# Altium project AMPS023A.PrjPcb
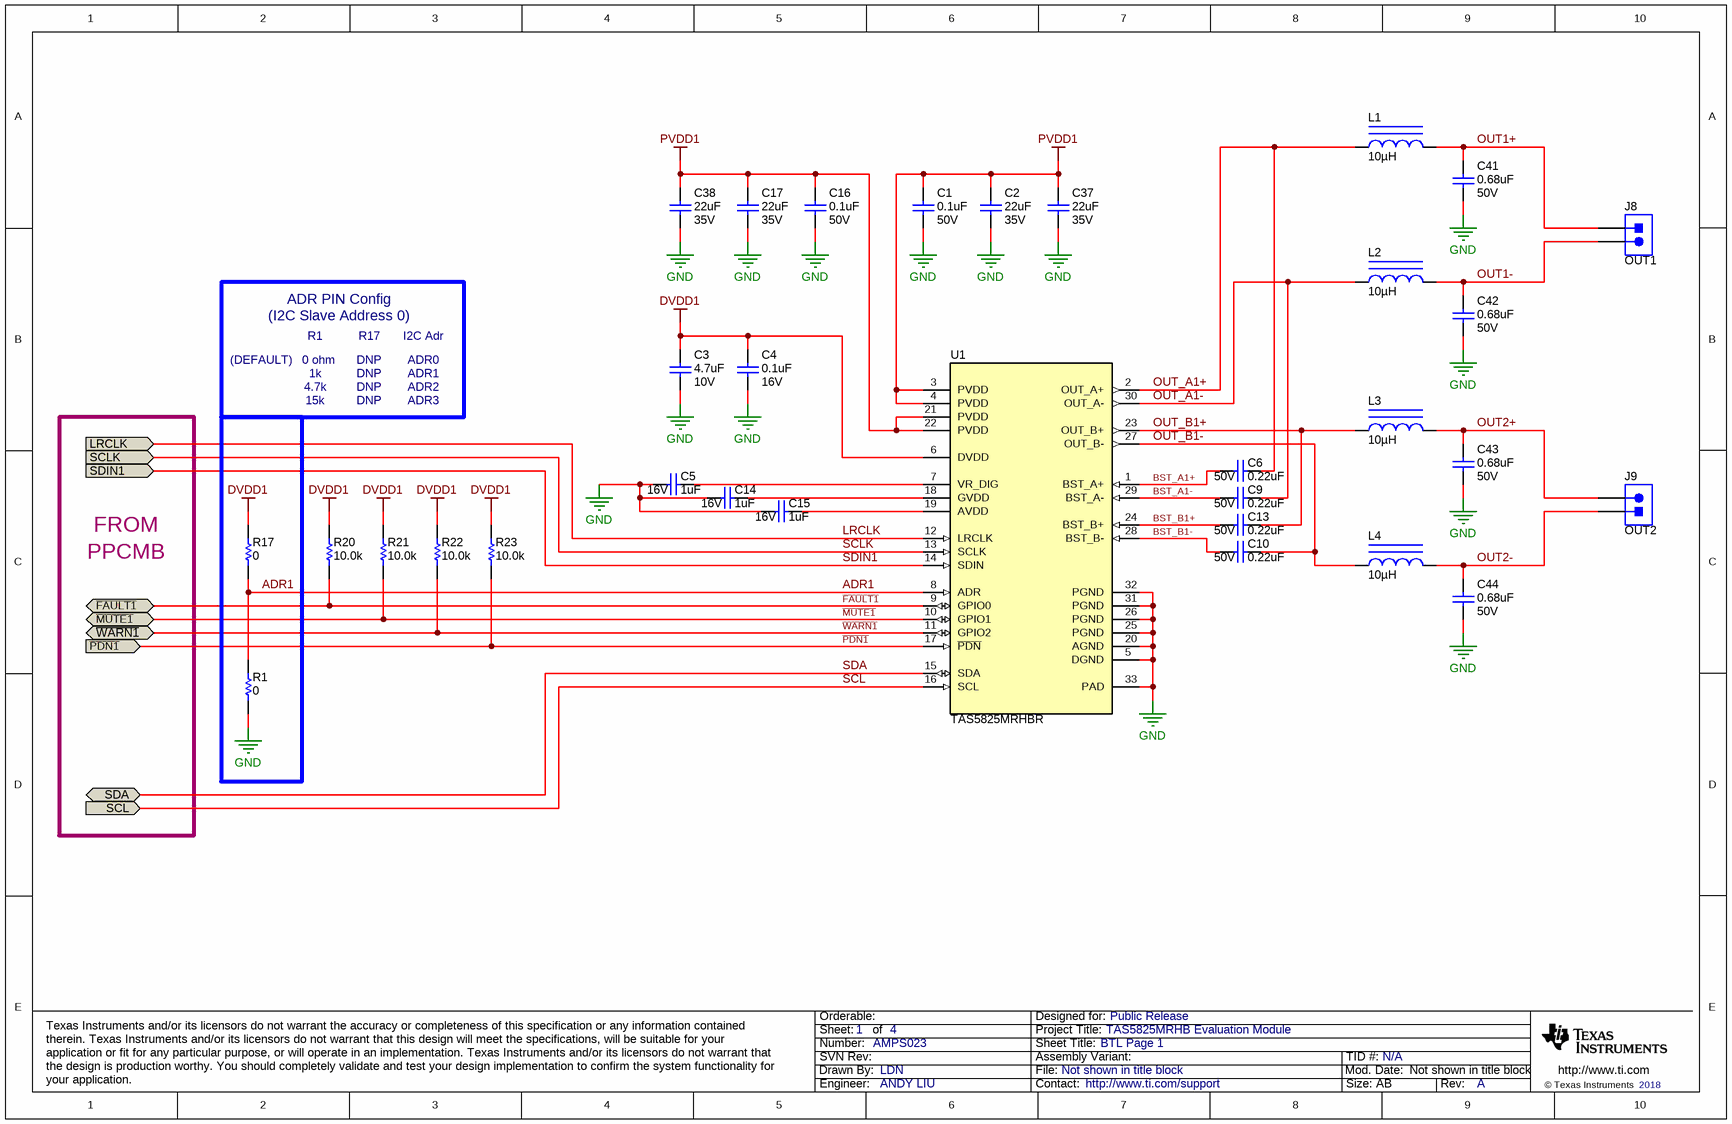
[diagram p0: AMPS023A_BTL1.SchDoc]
CopyrightYear: 2018; PCB_Layout: LDN; PCB_Rev: A; PRJ_Customer: Public Release; PRJ_Engineer: ANDY LIU; PRJ_Number: AMPS023; PRJ_Title: TAS5825MRHB Evaluation Module; SCH_Rev: A; TechSupport: http://www.ti.com/support; TID: N/A
4 sheets, 140 parts. Net scope: flat (ports and power ports of the same name join across sheets).
Board file: AMPS023A_PCB.PcbDoc
Sheets:
  AMPS023A_BTL1.SchDoc
  AMPS023A_BTL2.SchDoc
  AMPS023A_PPCMB-IO.SchDoc
  AMPS023A_EVM_Hardware.SchDoc

## Sheet AMPS023A_BTL1.SchDoc: BTL Page 1
size 323 x 209 mm; Date: Not shown in title block; ApprovedBy: Not shown in title block; CheckedBy: Not shown in title block; Author: Not shown in title block; CompanyName: Not shown in title block; DrawnBy: LDN; Engineer: Not shown in title block; Organization: Not shown in title block; Address1: Not shown in title block; Address2: Not shown in title block; Address3: Not shown in title block; Address4: Not shown in title block; DocumentNumber: 1; Revision: Use project parameter SCH_Rev; SheetNumber: 1; SheetTotal: 4; PageSetup: Record=PageOptions¦CenterHorizontal=True¦CenterVertical=True¦PrintScale=1.00¦XCorrection=1.00¦YCorrection=1.00¦PrintKind=0¦BorderSize=5000000¦LeftOffset=0¦BottomOffset=0¦Orientation=2¦PaperLength=1000¦PaperWidth=1000¦Scale=100¦PaperSource=15¦PrintQuality=600¦MediaType=1¦DitherType=10¦PaperKind=Letter¦PrintScaleMode=1

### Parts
C1  VDC_V: 50V  ValueDisplayed: 0.1uF  [0402L]  (hidden comment: C1005X7R1H104K050BB)
C2  VDC_V: 35V  ValueDisplayed: 22uF  [0805_KTR]  (hidden comment: C2012JB1V226M125AC)
C3  VDC_V: 10V  ValueDisplayed: 4.7uF  [0603L]  (hidden comment: C0603C475K8PACTU)
C4  VDC_V: 16V  ValueDisplayed: 0.1uF  [0603L]  (hidden comment: C0603C104K4RACTU)
C5  VDC_V: 16V  ValueDisplayed: 1uF  [0603L]  (hidden comment: C0603C105K4PACTU)
C6  VDC_V: 50V  ValueDisplayed: 0.22uF  [0603L]  (hidden comment: C1608X7R1H224K080AB)
C9  VDC_V: 50V  ValueDisplayed: 0.22uF  [0603L]  (hidden comment: C1608X7R1H224K080AB)
C10  VDC_V: 50V  ValueDisplayed: 0.22uF  [0603L]  (hidden comment: C1608X7R1H224K080AB)
C13  VDC_V: 50V  ValueDisplayed: 0.22uF  [0603L]  (hidden comment: C1608X7R1H224K080AB)
C14  VDC_V: 16V  ValueDisplayed: 1uF  [0603L]  (hidden comment: C0603C105K4PACTU)
C15  VDC_V: 16V  ValueDisplayed: 1uF  [0603L]  (hidden comment: C0603C105K4PACTU)
C16  VDC_V: 50V  ValueDisplayed: 0.1uF  [0402L]  (hidden comment: C1005X7R1H104K050BB)
C17  VDC_V: 35V  ValueDisplayed: 22uF  [0805_KTR]  (hidden comment: C2012JB1V226M125AC)
C37  VDC_V: 35V  ValueDisplayed: 22uF  [0805_KTR]  (hidden comment: C2012JB1V226M125AC)
C38  VDC_V: 35V  ValueDisplayed: 22uF  [0805_KTR]  (hidden comment: C2012JB1V226M125AC)
C41  VDC_V: 50V  ValueDisplayed: 0.68uF  [0805_KTR]  (hidden comment: C0805C684K5RACTU)
C42  VDC_V: 50V  ValueDisplayed: 0.68uF  [0805_KTR]  (hidden comment: C0805C684K5RACTU)
C43  VDC_V: 50V  ValueDisplayed: 0.68uF  [0805_KTR]  (hidden comment: C0805C684K5RACTU)
C44  VDC_V: 50V  ValueDisplayed: 0.68uF  [0805_KTR]  (hidden comment: C0805C684K5RACTU)
J8  OUT1  [JST_B2PS-VH]
J9  OUT2  [JST_B2PS-VH]
L1  ValueDisplayed: 10µH  [DEM10050C]  (hidden comment: 1274AS-H-100M=P3)
L2  ValueDisplayed: 10µH  [DEM10050C]  (hidden comment: 1274AS-H-100M=P3)
L3  ValueDisplayed: 10µH  [DEM10050C]  (hidden comment: 1274AS-H-100M=P3)
L4  ValueDisplayed: 10µH  [DEM10050C]  (hidden comment: 1274AS-H-100M=P3)
R1  ValueDisplayed: 0  [0402L]
R17  ValueDisplayed: 0  [0402L]  (hidden comment: DNP)
R20  ValueDisplayed: 10.0k  [0402L]  (hidden comment: RMCF0402FT10K0)
R21  ValueDisplayed: 10.0k  [0402L]  (hidden comment: RMCF0402FT10K0)
R22  ValueDisplayed: 10.0k  [0402L]  (hidden comment: RMCF0402FT10K0)
R23  ValueDisplayed: 10.0k  [0402L]  (hidden comment: RMCF0402FT10K0)
U1  TAS5825MRHBR  [RHB0032N]

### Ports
LRCLK (in), SCL (in), SCLK (in), SDA (bidir), SDIN1 (in), ~{FAULT1} (bidir), ~{MUTE1} (bidir), ~{PDN1} (in), ~{WARN1} (bidir)

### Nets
DVDD1: C3.2 C4.1 R17.2 R20.2 R21.2 R22.2 R23.2 U1.6(DVDD)
GND: C1.2 C2.1 C3.1 C4.2 C5.2 C14.2 C15.2 C16.2 C17.1 C37.1 C38.1 C41.2 C42.2 C43.2 C44.2 R1.2 U1.5(DGND) U1.20(AGND) U1.25(PGND) U1.26(PGND) U1.31(PGND) U1.32(PGND) U1.33(PAD)
PVDD1: C1.1 C2.2 C16.1 C17.2 C37.2 C38.2 U1.3(PVDD) U1.4(PVDD) U1.21(PVDD) U1.22(PVDD)
~{FAULT1}: R20.1 U1.9(GPIO0) ; port ~{FAULT1}
~{MUTE1}: R21.1 U1.10(GPIO1) ; port ~{MUTE1}
~{PDN1}: R23.1 U1.17(~{PDN}) ; port ~{PDN1}
~{WARN1}: R22.1 U1.11(GPIO2) ; port ~{WARN1}
ADR1: R1.1 R17.1 U1.8(ADR)
BST_A1+: C6.1 U1.1(BST_A+)
BST_A1-: C9.1 U1.29(BST_A-)
BST_B1+: C13.1 U1.24(BST_B+)
BST_B1-: C10.1 U1.28(BST_B-)
LRCLK: U1.12(LRCLK) ; port LRCLK
OUT1+: C41.1 J8.1 L1.2
OUT1-: C42.1 J8.2 L2.2
OUT2+: C43.1 J9.2 L3.2
OUT2-: C44.1 J9.1 L4.2
OUT_A1+: C6.2 L1.1 U1.2(OUT_A+)
OUT_A1-: C9.2 L2.1 U1.30(OUT_A-)
OUT_B1+: C13.2 L3.1 U1.23(OUT_B+)
OUT_B1-: C10.2 L4.1 U1.27(OUT_B-)
SCL: U1.16(SCL) ; port SCL
SCLK: U1.13(SCLK) ; port SCLK
SDA: U1.15(SDA) ; port SDA
SDIN1: U1.14(SDIN) ; port SDIN1
NetC5_1: C5.1 U1.7(VR_DIG)
NetC14_1: C14.1 U1.18(GVDD)
NetC15_1: C15.1 U1.19(AVDD)

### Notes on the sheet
- R1
- (I2C Slave Address 0)
- ADR PIN Config
- R17
- I2C Adr
- (DEFAULT)
- 1k
- 4.7k
- 15k
- 0 ohm
- DNP
- ADR0
- ADR1
- ADR2
- ADR3
- FROM
- PPCMB

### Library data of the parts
C1 C16 = CMP-0006297-2: CAP, CERM, 0.1 uF, 50 V, +/- 10%, X7R, 0402; Manufacturer: TDK; TaMin_C: -55°C; ESR_ohm: 0.039064; Polarized: N; SizeAreaWB_mm2: 3; Value1: 0.039064 ohm; U/M: EA; Value: 0.1uF; TaMax_C: 125°C; SizeZ_mm: 0.6; SizeX_mm: 1; SizeY_mm: 0.5; Cap_Case: 0402; CompType: Capacitor; Cap_F: 100nF; IRMS_A: 8.14669dA; AEC Category: Q200
C2 C17 C37 C38 = CMP-0007821-1: CAP, CERM, 22 uF, 35 V, +/- 20%, JB, 0805; Manufacturer: TDK; TaMin_C: -25°C; Polarized: N; SizeAreaWB_mm2: 6.75; Value1: Unknown; U/M: EA; Value: 22uF; TaMax_C: 85°C; SizeZ_mm: 1.45; SizeX_mm: 2; SizeY_mm: 1.25; Cap_Case: 0805; SizeArea_mm2: 2.5; CompType: Capacitor; Cap_F: 22µF; AEC Category: Q200
C3 = CMP-0006949-5: CAP, CERM, 4.7 uF, 10 V, +/- 10%, X5R, 0603; Manufacturer: Kemet; TaMin_C: -55°C; ESR_ohm: 6m; Polarized: N; SizeAreaWB_mm2: 4.68; Value1: 0.006 ohm; U/M: EA; Value: 4.7uF; TaMax_C: 85°C; SizeZ_mm: 1; SizeX_mm: 1.6; SizeY_mm: 0.8; Cap_Case: 0603; SizeArea_mm2: 1.28; CompType: Capacitor; Cap_F: 4.7µF; IRMS_A: 7.24A; AEC Category: Q200
C4 = CMP-0006860-5: CAP, CERM, 0.1 uF, 16 V, +/- 10%, X7R, 0603; Manufacturer: Kemet; TaMin_C: -55°C; Polarized: N; SizeAreaWB_mm2: 4.68; Value1: Unknown; U/M: EA; Value: 0.1uF; TaMax_C: 125°C; SizeZ_mm: 1; SizeX_mm: 1.6; SizeY_mm: 0.8; Cap_Case: 0603; SizeArea_mm2: 1.28; CompType: Capacitor; Cap_F: 100nF; AEC Category: Q200
C5 = CMP-0006868-5: CAP, CERM, 1 uF, 16 V, +/- 10%, X5R, 0603; Manufacturer: Kemet; TaMin_C: -55°C; Polarized: N; SizeAreaWB_mm2: 4.68; Value1: Unknown; U/M: EA; Value: 1uF; TaMax_C: 85°C; SizeZ_mm: 1; SizeX_mm: 1.6; SizeY_mm: 0.8; Cap_Case: 0603; SizeArea_mm2: 1.28; Cap_F: 1µF; AEC Category: Q200
C6 C9 C10 C13 = CMP-0007047-4: CAP, CERM, 0.22 uF, 50 V, +/- 10%, X7R, 0603; Manufacturer: TDK; TaMin_C: -55°C; ESR_ohm: 0.021699; Polarized: N; SizeAreaWB_mm2: 4.68; Value1: 0.021699 ohm; U/M: EA; Value: 0.22uF; TaMax_C: 125°C; SizeZ_mm: 1; SizeX_mm: 1.6; SizeY_mm: 0.8; Cap_Case: 0603; SizeArea_mm2: 1.28; CompType: Capacitor; Cap_F: 220nF; IRMS_A: 1.12496A; AEC Category: Q200
C14 C15 = CMP-0006868-5: CAP, CERM, 1 uF, 16 V, +/- 10%, X5R, 0603; Manufacturer: Kemet; TaMin_C: -55°C; Polarized: N; SizeAreaWB_mm2: 4.68; Value1: Unknown; U/M: EA; Value: 1uF; TaMax_C: 85°C; SizeZ_mm: 1; SizeX_mm: 1.6; SizeY_mm: 0.8; Cap_Case: 0603; SizeArea_mm2: 1.28; CompType: Capacitor; Cap_F: 1µF; AEC Category: Q200
C41-C44 = CMP-0007814-2: CAP, CERM, 0.68 uF, 50 V, +/- 10%, X7R, 0805; Manufacturer: Kemet; TaMin_C: -55°C; Polarized: N; SizeAreaWB_mm2: 6.75; Value1: Unknown; U/M: EA; Value: 0.68uF; TaMax_C: 125°C; SizeZ_mm: 1.45; SizeX_mm: 2; SizeY_mm: 1.25; Cap_Case: 0805; SizeArea_mm2: 2.5; CompType: Capacitor; Cap_F: 680nF; AEC Category: Q200
J8 J9 = CMP-0074989-1: Header (friction lock), 3.96mm, 2x1, Tin, R/A, TH; Manufacturer: JST Manufacturing; PartNumber: B2PS-VH(LF)(SN); CNHeader: False; Green_Lifecycle: Active; Green_REACh: Passed
L1-L4 = CMP-0077807-1: Inductor, Shielded, Ferrite, 10 µH, 4.4 A, 0.0304 ohm, SMD; Manufacturer: MuRata; Isat: 6.2A @ 30% inductance drop; Irms: 4.4A @ 40C rise; SizeAreaWB_mm2: 144.0; DCR_ohm: 0.0304; Value: 10uH; Imax_A: 4.4A; SizeZ_mm: 5.0; SizeX_mm: 10.0; SizeArea_mm2: 100.0; AEC Qualified: N; AEC Category: Q200
R1 R17 = CMP-0026992-2: RES, 0, 5%, 0.063 W, 0402; Manufacturer: Panasonic; PartNumber: ERJ-2GE0R00X; Power_W: 63mW; TempCo: 600 ppm/C; Value_Code: 0000; U/M: EA; Value: 0; EIA_Code: E24; SizeX_mm: 1; SizeY_mm: 0.5; SizeZ_mm: 0.6; Value2: 0.063W; CompType: Resistor; VDC_V: 50V; AEC Category: Q200
R20-R23 = CMP-0026754-1: RES, 10.0 k, 1%, 0.063 W, AEC-Q200 Grade 0, 0402; Manufacturer: Stackpole Electronics Inc; Power_W: 63mW; TempCo: 100 ppm/C; Value_Code: 10k0; U/M: EA; Value: 10.0k; EIA_Code: E96; Res_ohm: 10k; SizeX_mm: 1; SizeY_mm: 0.5; SizeZ_mm: 0.6; Value2: 0.063W; CompType: Resistor; AEC Qualified: Y; VDC_V: 50V; AEC Grade: 0; AEC Category: Q200
U1 = CMP-0077820-2: 4.5 V to 26.4 V, Inductor-Less, Digital Input, Stereo, Closed-Loop Class-D Audio Amplifier with 96-kHz/192-kHz Extended Audio Processing, RHB0032N (VQFN-32); Alternate PartNumber: TAS5825MRHBT; Alternate Manufacturer: Texas Instruments; SizeAreaWB_mm2: 49.0; SizeZ_mm: 0.9; SizeX_mm: 5.0; SizeArea_mm2: 25.0; CompType: IC; AEC Qualified: N; AEC Category: Q200

## Sheet AMPS023A_BTL2.SchDoc: BTL Page 2
size 323 x 209 mm; Date: Not shown in title block; ApprovedBy: Not shown in title block; CheckedBy: Not shown in title block; Author: Not shown in title block; CompanyName: Not shown in title block; DrawnBy: LDN; Engineer: Not shown in title block; Organization: Not shown in title block; Address1: Not shown in title block; Address2: Not shown in title block; Address3: Not shown in title block; Address4: Not shown in title block; DocumentNumber: 2; Revision: Use project parameter SCH_Rev; SheetNumber: 2; SheetTotal: 4; PageSetup: Record=PageOptions¦CenterHorizontal=True¦CenterVertical=True¦PrintScale=1.00¦XCorrection=1.00¦YCorrection=1.00¦PrintKind=0¦BorderSize=5000000¦LeftOffset=0¦BottomOffset=0¦Orientation=2¦PaperLength=1000¦PaperWidth=1000¦Scale=100¦PaperSource=15¦PrintQuality=600¦MediaType=1¦DitherType=10¦PaperKind=Letter¦PrintScaleMode=1
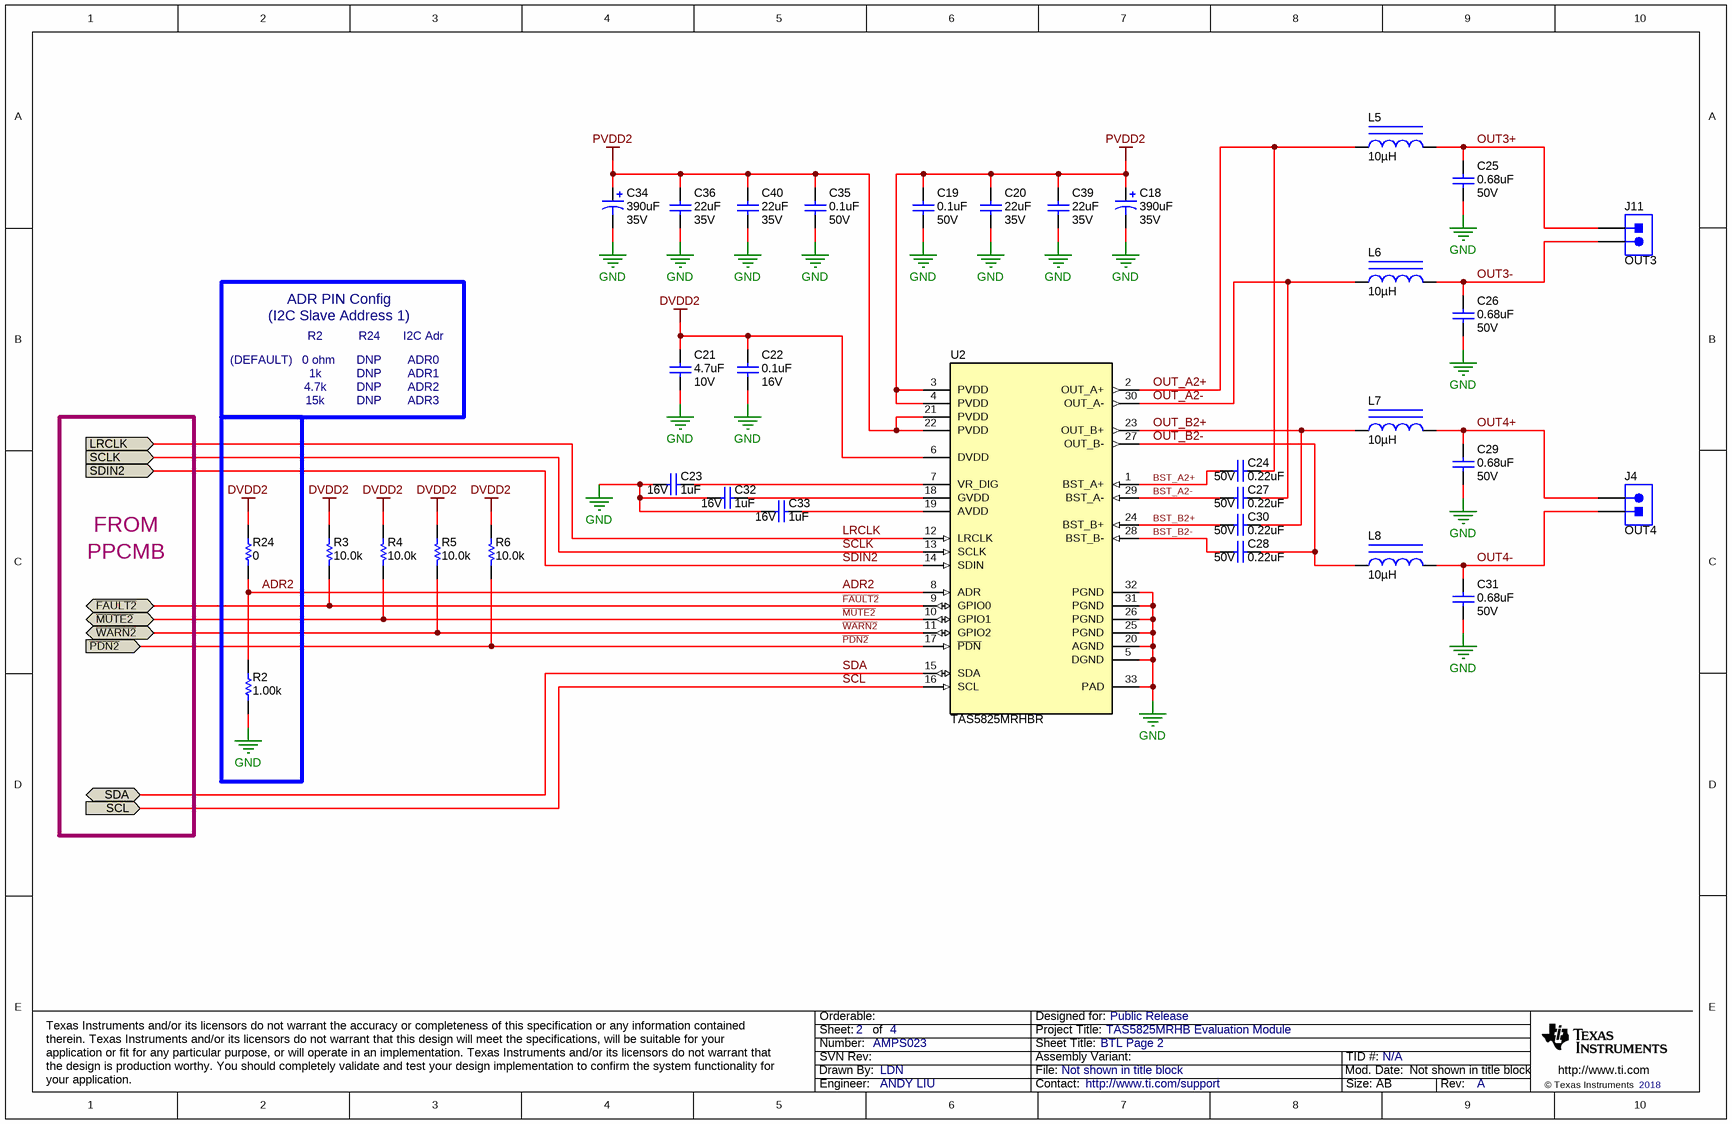
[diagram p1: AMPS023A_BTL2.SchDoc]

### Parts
C18  VDC_V: 35V  ValueDisplayed: 390uF  [SM_RADIAL_10BMM]  (hidden comment: +)
C19  VDC_V: 50V  ValueDisplayed: 0.1uF  [0402L]  (hidden comment: C1005X7R1H104K050BB)
C20  VDC_V: 35V  ValueDisplayed: 22uF  [0805_KTR]  (hidden comment: C2012JB1V226M125AC)
C21  VDC_V: 10V  ValueDisplayed: 4.7uF  [0603L]  (hidden comment: C0603C475K8PACTU)
C22  VDC_V: 16V  ValueDisplayed: 0.1uF  [0603L]  (hidden comment: C0603C104K4RACTU)
C23  VDC_V: 16V  ValueDisplayed: 1uF  [0603L]  (hidden comment: C0603C105K4PACTU)
C24  VDC_V: 50V  ValueDisplayed: 0.22uF  [0603L]  (hidden comment: C1608X7R1H224K080AB)
C25  VDC_V: 50V  ValueDisplayed: 0.68uF  [0805_KTR]  (hidden comment: C0805C684K5RACTU)
C26  VDC_V: 50V  ValueDisplayed: 0.68uF  [0805_KTR]  (hidden comment: C0805C684K5RACTU)
C27  VDC_V: 50V  ValueDisplayed: 0.22uF  [0603L]  (hidden comment: C1608X7R1H224K080AB)
C28  VDC_V: 50V  ValueDisplayed: 0.22uF  [0603L]  (hidden comment: C1608X7R1H224K080AB)
C29  VDC_V: 50V  ValueDisplayed: 0.68uF  [0805_KTR]  (hidden comment: C0805C684K5RACTU)
C30  VDC_V: 50V  ValueDisplayed: 0.22uF  [0603L]  (hidden comment: C1608X7R1H224K080AB)
C31  VDC_V: 50V  ValueDisplayed: 0.68uF  [0805_KTR]  (hidden comment: C0805C684K5RACTU)
C32  VDC_V: 16V  ValueDisplayed: 1uF  [0603L]  (hidden comment: C0603C105K4PACTU)
C33  VDC_V: 16V  ValueDisplayed: 1uF  [0603L]  (hidden comment: C0603C105K4PACTU)
C34  VDC_V: 35V  ValueDisplayed: 390uF  [SM_RADIAL_10BMM]  (hidden comment: +)
C35  VDC_V: 50V  ValueDisplayed: 0.1uF  [0402L]  (hidden comment: C1005X7R1H104K050BB)
C36  VDC_V: 35V  ValueDisplayed: 22uF  [0805_KTR]  (hidden comment: C2012JB1V226M125AC)
C39  VDC_V: 35V  ValueDisplayed: 22uF  [0805_KTR]  (hidden comment: C2012JB1V226M125AC)
C40  VDC_V: 35V  ValueDisplayed: 22uF  [0805_KTR]  (hidden comment: C2012JB1V226M125AC)
J4  OUT4  [JST_B2PS-VH]
J11  OUT3  [JST_B2PS-VH]
L5  ValueDisplayed: 10µH  [DEM10050C]  (hidden comment: 1274AS-H-100M=P3)
L6  ValueDisplayed: 10µH  [DEM10050C]  (hidden comment: 1274AS-H-100M=P3)
L7  ValueDisplayed: 10µH  [DEM10050C]  (hidden comment: 1274AS-H-100M=P3)
L8  ValueDisplayed: 10µH  [DEM10050C]  (hidden comment: 1274AS-H-100M=P3)
R2  ValueDisplayed: 1.00k  [0402L]  (hidden comment: ERA-2AEB102X)
R3  ValueDisplayed: 10.0k  [0402L]  (hidden comment: RMCF0402FT10K0)
R4  ValueDisplayed: 10.0k  [0402L]  (hidden comment: RMCF0402FT10K0)
R5  ValueDisplayed: 10.0k  [0402L]  (hidden comment: RMCF0402FT10K0)
R6  ValueDisplayed: 10.0k  [0402L]  (hidden comment: RMCF0402FT10K0)
R24  ValueDisplayed: 0  [0402L]  (hidden comment: DNP)
U2  TAS5825MRHBR  [RHB0032N]

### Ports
LRCLK (in), SCL (in), SCLK (in), SDA (bidir), SDIN2 (in), ~{FAULT2} (bidir), ~{MUTE2} (bidir), ~{PDN2} (in), ~{WARN2} (bidir)

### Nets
DVDD2: C21.2 C22.1 R3.2 R4.2 R5.2 R6.2 R24.2 U2.6(DVDD)
GND: C18.2(-) C19.2 C20.1 C21.1 C22.2 C23.2 C25.2 C26.2 C29.2 C31.2 C32.2 C33.2 C34.2(-) C35.2 C36.1 C39.1 C40.1 R2.2 U2.5(DGND) U2.20(AGND) U2.25(PGND) U2.26(PGND) U2.31(PGND) U2.32(PGND) U2.33(PAD)
PVDD2: C18.1(+) C19.1 C20.2 C34.1(+) C35.1 C36.2 C39.2 C40.2 U2.3(PVDD) U2.4(PVDD) U2.21(PVDD) U2.22(PVDD)
~{FAULT2}: R3.1 U2.9(GPIO0) ; port ~{FAULT2}
~{MUTE2}: R4.1 U2.10(GPIO1) ; port ~{MUTE2}
~{PDN2}: R6.1 U2.17(~{PDN}) ; port ~{PDN2}
~{WARN2}: R5.1 U2.11(GPIO2) ; port ~{WARN2}
ADR2: R2.1 R24.1 U2.8(ADR)
BST_A2+: C24.1 U2.1(BST_A+)
BST_A2-: C27.1 U2.29(BST_A-)
BST_B2+: C30.1 U2.24(BST_B+)
BST_B2-: C28.1 U2.28(BST_B-)
LRCLK: U2.12(LRCLK) ; port LRCLK
OUT3+: C25.1 J11.1 L5.2
OUT3-: C26.1 J11.2 L6.2
OUT4+: C29.1 J4.2 L7.2
OUT4-: C31.1 J4.1 L8.2
OUT_A2+: C24.2 L5.1 U2.2(OUT_A+)
OUT_A2-: C27.2 L6.1 U2.30(OUT_A-)
OUT_B2+: C30.2 L7.1 U2.23(OUT_B+)
OUT_B2-: C28.2 L8.1 U2.27(OUT_B-)
SCL: U2.16(SCL) ; port SCL
SCLK: U2.13(SCLK) ; port SCLK
SDA: U2.15(SDA) ; port SDA
SDIN2: U2.14(SDIN) ; port SDIN2
NetC23_1: C23.1 U2.7(VR_DIG)
NetC32_1: C32.1 U2.18(GVDD)
NetC33_1: C33.1 U2.19(AVDD)

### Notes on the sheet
- R2
- (I2C Slave Address 1)
- ADR PIN Config
- R24
- I2C Adr
- (DEFAULT)
- 1k
- 4.7k
- 15k
- 0 ohm
- DNP
- ADR0
- ADR1
- ADR2
- ADR3
- FROM
- PPCMB

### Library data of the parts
C18 C34 = CMP-0011092-1: CAP, AL, 390 uF, 35 V, +/- 20%, 0.08 ohm, SMD; Manufacturer: Nichicon; PartNumber: UCL1V391MNL1GS; TaMin_C: -55°C; ESR_ohm: 0.08; Polarized: Y; SizeAreaWB_mm2: 159.9; U/M: EA; Value: 390uF; TaMax_C: 105°C; SizeZ_mm: 10.2; SizeX_mm: 11; SizeY_mm: 10.3; Cap_Case: 10x10; SizeArea_mm2: 113.3; CompType: Capacitor; Cap_F: 390µF; IRMS_A: 8.5dA; AEC Category: Q200
C19 C35 = CMP-0006297-2: as C1 on sheet AMPS023A_BTL1
C20 C36 C39 C40 = CMP-0007821-1: as C2 on sheet AMPS023A_BTL1
C21 = CMP-0006949-5: as C3 on sheet AMPS023A_BTL1
C22 = CMP-0006860-5: as C4 on sheet AMPS023A_BTL1
C23 C32 C33 = CMP-0006868-5: as C14 on sheet AMPS023A_BTL1
C24 C27 C28 C30 = CMP-0007047-4: as C6 on sheet AMPS023A_BTL1
C25 C26 C29 C31 = CMP-0007814-2: as C41 on sheet AMPS023A_BTL1
J4 J11 = CMP-0074989-1: as J8 on sheet AMPS023A_BTL1
L5-L8 = CMP-0077807-1: as L1 on sheet AMPS023A_BTL1
R2 = CMP-0026770-1: RES, 1.00 k, 0.1%, 0.063 W, 0402; Manufacturer: Panasonic; Power_W: 63mW; TempCo: 25 ppm/C; Value_Code: 1k00; U/M: EA; Value: 1.00k; EIA_Code: E192; Res_ohm: 1k; SizeX_mm: 1; SizeY_mm: 0.5; SizeZ_mm: 0.6; Value2: 0.063W; CompType: Resistor; VDC_V: 50V; AEC Category: Q200
R3-R6 = CMP-0026754-1: as R20 on sheet AMPS023A_BTL1
R24 = CMP-0026992-2: as R1 on sheet AMPS023A_BTL1
U2 = CMP-0077820-2: as U1 on sheet AMPS023A_BTL1

## Sheet AMPS023A_PPCMB-IO.SchDoc: PUREPATH CTRL CONSOLE MOTHERBRD I/O
size 431 x 279 mm; Date: Not shown in title block; ApprovedBy: Not shown in title block; CheckedBy: Not shown in title block; Author: Not shown in title block; CompanyName: Not shown in title block; DrawnBy: LDN; Organization: Not shown in title block; Address1: Not shown in title block; Address2: Not shown in title block; Address3: Not shown in title block; Address4: Not shown in title block; DocumentNumber: 3; Revision: Use project parameter SCH_Rev; SheetNumber: 3; SheetTotal: 4; PageSetup: Record=PageOptions¦CenterHorizontal=True¦CenterVertical=True¦PrintScale=1.00¦XCorrection=1.00¦YCorrection=1.00¦PrintKind=0¦BorderSize=5000000¦LeftOffset=0¦BottomOffset=0¦Orientation=2¦PaperLength=1000¦PaperWidth=1000¦Scale=100¦PaperSource=15¦PrintQuality=600¦MediaType=1¦DitherType=10¦PaperKind=Letter¦PrintScaleMode=1
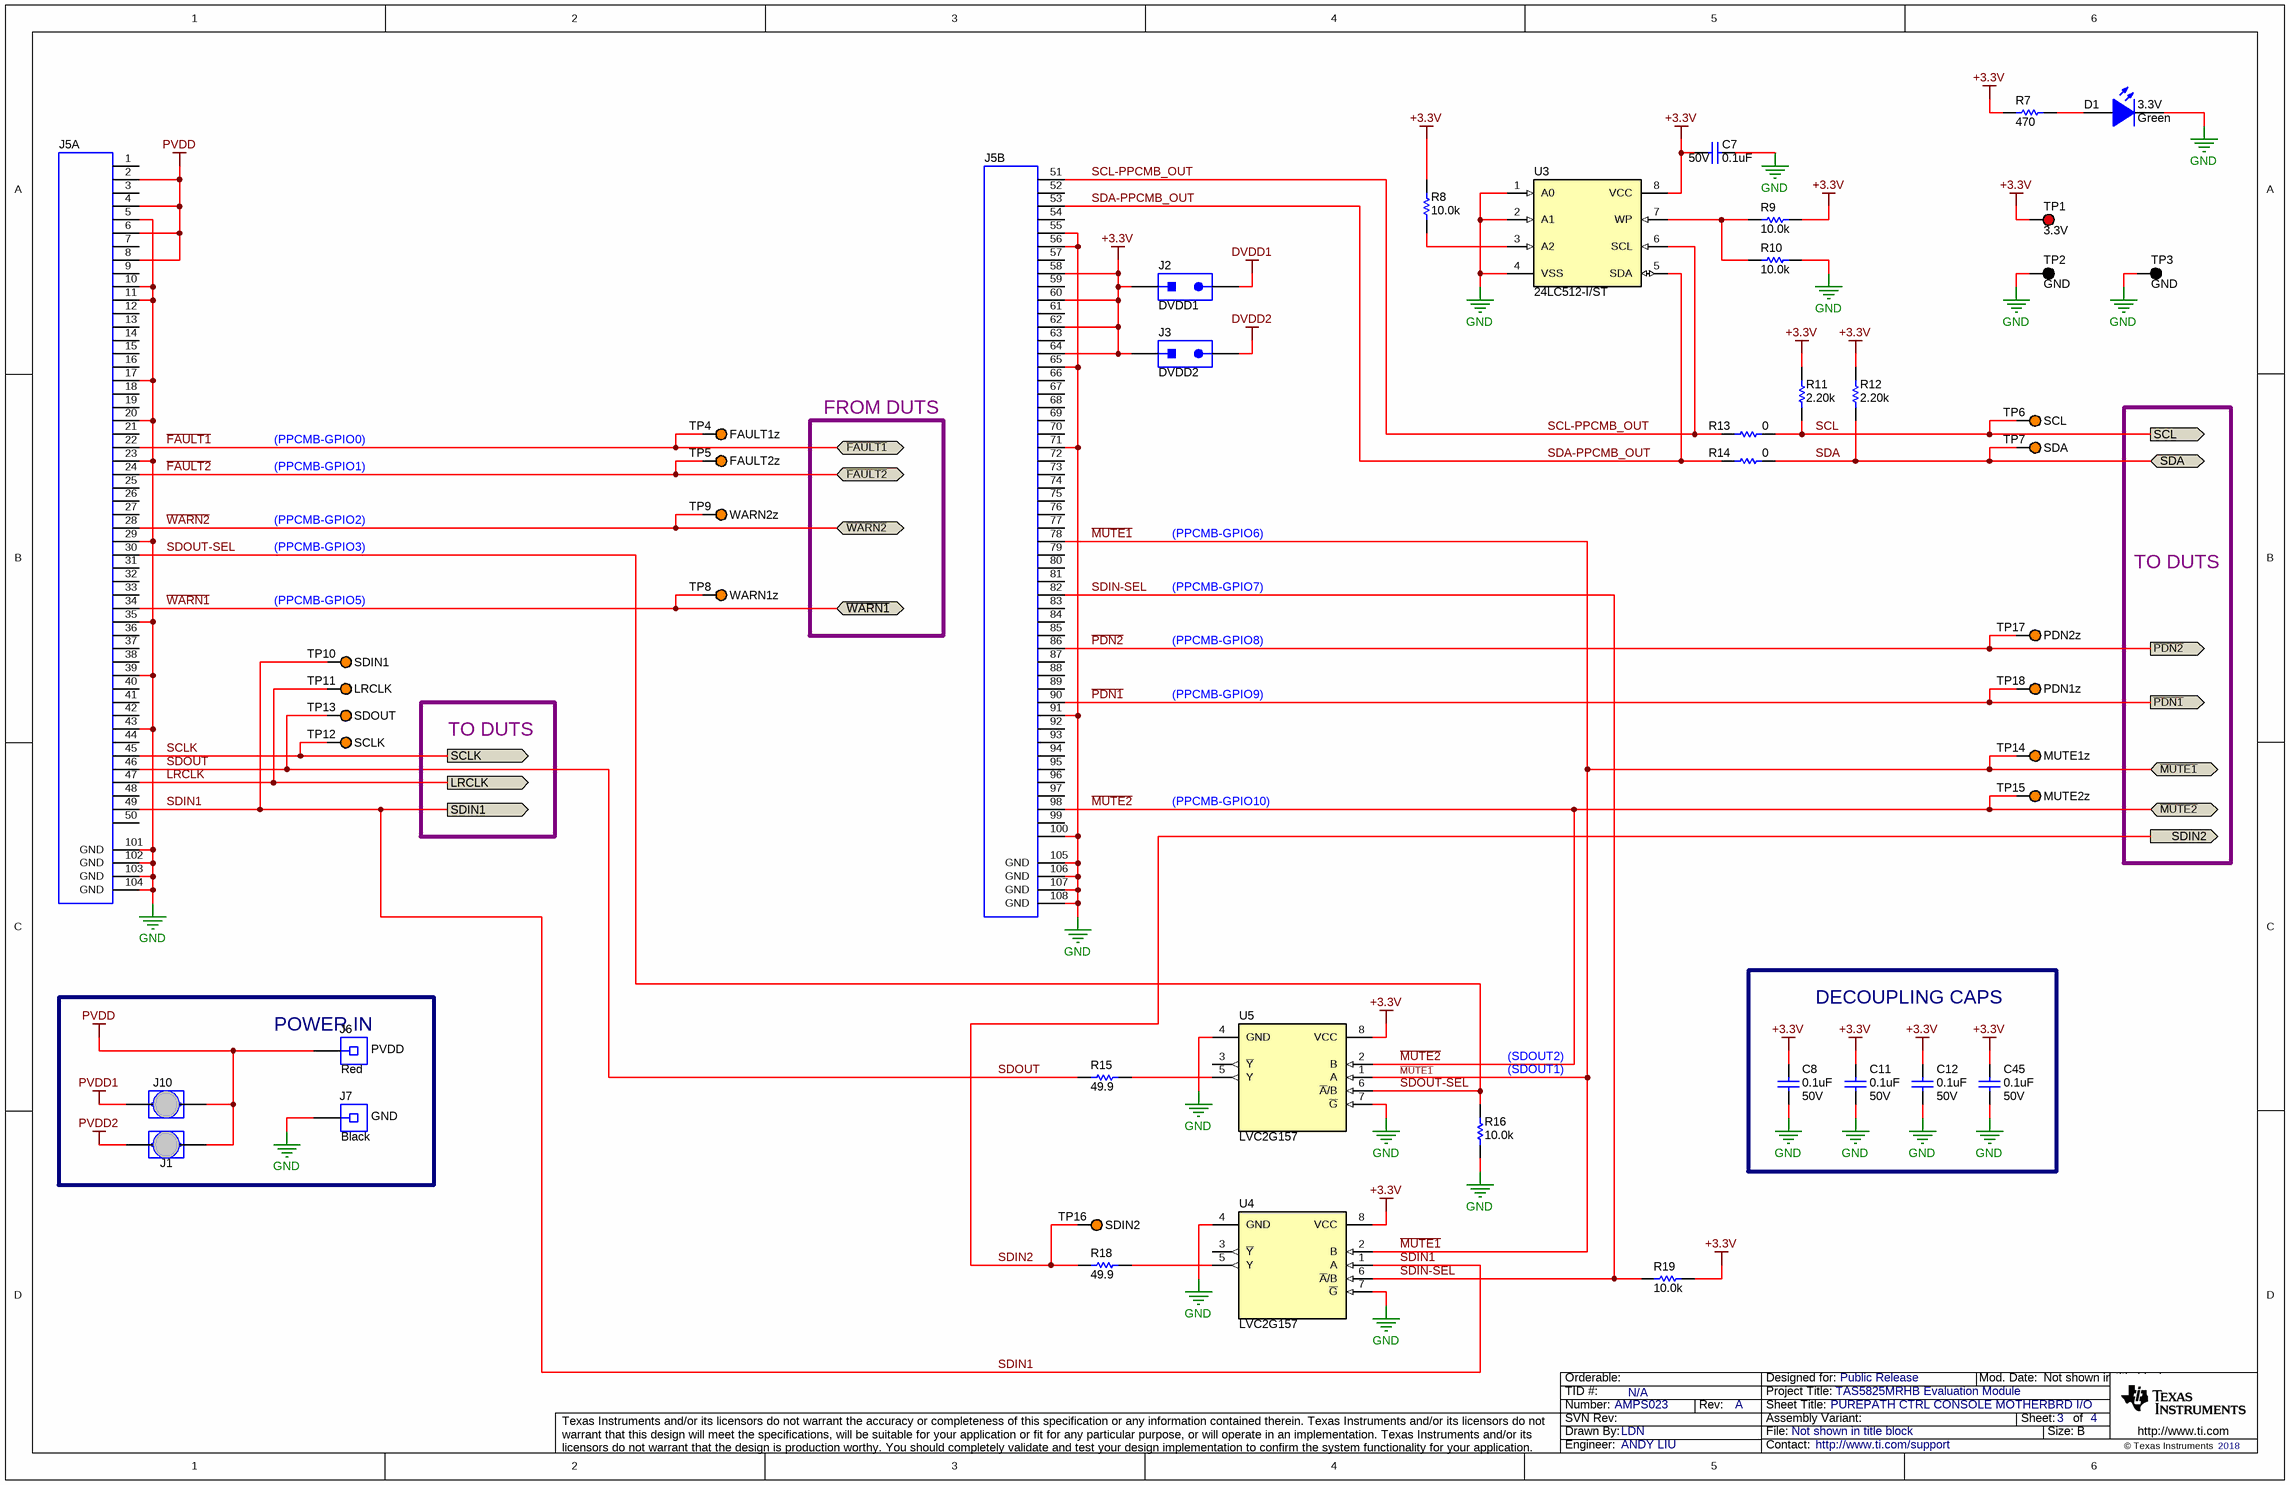
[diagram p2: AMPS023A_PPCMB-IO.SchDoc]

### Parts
C7  VDC_V: 50V  ValueDisplayed: 0.1uF  [0402L]  (hidden comment: C1005X7R1H104K050BB)
C8  VDC_V: 50V  ValueDisplayed: 0.1uF  [0402L]  (hidden comment: C1005X7R1H104K050BB)
C11  VDC_V: 50V  ValueDisplayed: 0.1uF  [0402L]  (hidden comment: C1005X7R1H104K050BB)
C12  VDC_V: 50V  ValueDisplayed: 0.1uF  [0402L]  (hidden comment: C1005X7R1H104K050BB)
C45  VDC_V: 50V  ValueDisplayed: 0.1uF  [0402L]  (hidden comment: C1005X7R1H104K050BB)
D1  3.3V  value Green  [LTST-C170KGKT_Green]
J1  (no value)  [HARWIN_S1911-46R]
J2  DVDD1  [Sullins_PBC02SAAN]
J3  DVDD2  [Sullins_PBC02SAAN]
J5  QTS-050-01-F-D-A  [CONN_QTS-050-01-F-D-A]  (value not drawn)  (parts A,B of 2)
J6  PVDD  Shell Color: Red  [Keystone_7006]
J7  GND  ShellColor: Black  [Keystone_7007]
J10  (no value)  [HARWIN_S1911-46R]
R7  ValueDisplayed: 470  [0402L]  (hidden comment: ERJ-2RKF4700X)
R8  ValueDisplayed: 10.0k  [0402L]  (hidden comment: RMCF0402FT10K0)
R9  ValueDisplayed: 10.0k  [0402L]  (hidden comment: DNP)
R10  ValueDisplayed: 10.0k  [0402L]  (hidden comment: RMCF0402FT10K0)
R11  ValueDisplayed: 2.20k  [0402L]  (hidden comment: RC0402FR-072K2L)
R12  ValueDisplayed: 2.20k  [0402L]  (hidden comment: RC0402FR-072K2L)
R13  ValueDisplayed: 0  [0603L]  (hidden comment: ERJ-3GEY0R00V)
R14  ValueDisplayed: 0  [0603L]  (hidden comment: ERJ-3GEY0R00V)
R15  ValueDisplayed: 49.9  [0402L]  (hidden comment: RC0402FR-0749R9L)
R16  ValueDisplayed: 10.0k  [0402L]  (hidden comment: RMCF0402FT10K0)
R18  ValueDisplayed: 49.9  [0402L]  (hidden comment: RC0402FR-0749R9L)
R19  ValueDisplayed: 10.0k  [0402L]  (hidden comment: RMCF0402FT10K0)
TP1  3.3V  [Keystone5000]
TP2  GND  [Keystone5001]
TP3  GND  [Keystone5001]
TP4  FAULT1z  [Keystone5003]
TP5  FAULT2z  [Keystone5003]
TP6  SCL  [Keystone5003]
TP7  SDA  [Keystone5003]
TP8  WARN1z  [Keystone5003]
TP9  WARN2z  [Keystone5003]
TP10  SDIN1  [Keystone5003]
TP11  LRCLK  [Keystone5003]
TP12  SCLK  [Keystone5003]
TP13  SDOUT  [Keystone5003]
TP14  MUTE1z  [Keystone5003]
TP15  MUTE2z  [Keystone5003]
TP16  SDIN2  [Keystone5003]
TP17  PDN2z  [Keystone5003]
TP18  PDN1z  [Keystone5003]
U3  24LC512-I/ST  [TSSOP-8]
U4  LVC2G157  [DCU0008A_N]
U5  LVC2G157  [DCU0008A_N]

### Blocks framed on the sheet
DECOUPLING CAPS: C8 C11 C12 C45
POWER IN: J1 J6 J7 J10

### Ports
LRCLK (out), SCL (out), SCLK (out), SDA (bidir), SDIN1 (out), SDIN2 (out), ~{FAULT1} (bidir), ~{FAULT2} (bidir), ~{MUTE1} (bidir), ~{MUTE2} (bidir), ~{PDN1} (out), ~{PDN2} (out), ~{WARN1} (bidir), ~{WARN2} (bidir)

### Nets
+3.3V: C7.1 C8.2 C11.2 C12.2 C45.2 J2.1 J3.1 J5.58 J5.60 J5.62 J5.64 R7.2 R8.2 R9.1 R11.2 R12.2 R19.1 TP1.1 U3.8(VCC) U4.8(VCC) U5.8(VCC)
DVDD1: J2.2
DVDD2: J3.2
GND: C7.2 C8.1 C11.1 C12.1 C45.1 D1.2(K) J5.5 J5.10 J5.11 J5.17 J5.20 J5.23 J5.29 J5.35 J5.39 J5.43 J5.55 J5.56 J5.65 J5.71 J5.91 J5.100 J5.101(GND) J5.102(GND) J5.103(GND) J5.104(GND) J5.105(GND) J5.106(GND) J5.107(GND) J5.108(GND) J7.1 R10.1 R16.2 TP2.1 TP3.1 U3.1(A0) U3.2(A1) U3.4(VSS) U4.4(GND) U4.7(~{G}) U5.4(GND) U5.7(~{G})
PVDD: J1.2 J5.2 J5.4 J5.6 J5.8 J6.1 J10.2
PVDD1: J10.1
PVDD2: J1.1
~{FAULT1}: J5.22 TP4.1 ; port ~{FAULT1}
~{FAULT2}: J5.24 TP5.1 ; port ~{FAULT2}
~{MUTE1}: J5.78 TP14.1 U4.2(B) U5.1(A) ; port ~{MUTE1}
~{MUTE2}: J5.98 TP15.1 U5.2(B) ; port ~{MUTE2}
~{PDN1}: J5.90 TP18.1 ; port ~{PDN1}
~{PDN2}: J5.86 TP17.1 ; port ~{PDN2}
~{WARN1}: J5.34 TP8.1 ; port ~{WARN1}
~{WARN2}: J5.28 TP9.1 ; port ~{WARN2}
LRCLK: J5.47 TP11.1 ; port LRCLK
SCL: R11.1 R13.1 TP6.1 ; port SCL
SCL-PPCMB_OUT: J5.51 R13.2 U3.6(SCL)
SCLK: J5.45 TP12.1 ; port SCLK
SDA: R12.1 R14.1 TP7.1 ; port SDA
SDA-PPCMB_OUT: J5.53 R14.2 U3.5(SDA)
SDIN1: J5.49 TP10.1 U4.1(A) ; port SDIN1
SDIN2: R18.2 TP16.1 ; port SDIN2
SDIN-SEL: J5.82 R19.2 U4.6(~{A}/B)
SDOUT: J5.46 R15.2 TP13.1
SDOUT-SEL: J5.30 R16.1 U5.6(~{A}/B)
NetD1_1: D1.1(A) R7.1
NetR8_1: R8.1 U3.3(A2)
NetR9_2: R9.2 R10.2 U3.7(WP)
NetR15_1: R15.1 U5.5(Y)
NetR18_1: R18.1 U4.5(Y)

Not connected (* = marked no-connect by the designer): J5 1 3 7 9 12 13 14 15 16 18 19 21 25 26 27 31 32 33 36 37 38 40 41 42 44 48 50 52(2) 54(4) 57(7) 59(9) 61(11) 63(13) 66(16) 67(17) 68(18) 69(19) 70(20) 72(22) 73(23) 74(24) 75(25) 76(26) 77(27) 79(29) 80(30) 81(31) 83(33) 84(34) 85(35) 87(37) 88(38) 89(39) 92(42) 93(43) 94(44) 95(45) 96(46) 97(47) 99(49); U4 3(~{Y}); U5 3(~{Y})

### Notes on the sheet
- FROM DUTS
- (PPCMB-GPIO0)
- (PPCMB-GPIO1)
- (PPCMB-GPIO3)
- (PPCMB-GPIO2)
- (PPCMB-GPIO6)
- TO DUTS
- (PPCMB-GPIO5)
- (PPCMB-GPIO7)
- (PPCMB-GPIO8)
- (PPCMB-GPIO9)
- (PPCMB-GPIO10)
- (near R16) (SDOUT1)
- (SDOUT2)

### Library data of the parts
C7 C8 C11 C12 C45 = CMP-0006297-2: as C1 on sheet AMPS023A_BTL1
D1 = CMP-0002888-1: LED, Green, SMD; Manufacturer: Lite-On; PartNumber: LTST-C170KGKT; Io_A: 20mA; Value1: W; U/M: EA; Vf_V: 2V; Type: AlInGaP
J1 J10 = CMP-0075020-1: JUMPER TIN SMD; Manufacturer: Harwin; PartNumber: S1911-46R; CNHeader: False; Green_Lifecycle: Active; Green_REACh: Passed; CompType: Jumper SMT
J2 J3 = CMP-0054566-1: Header, 100mil, 2x1, Gold, TH; Manufacturer: Sullins Connector Solutions; PartNumber: PBC02SAAN; CNHeader: TRUE; Current_A: 3A; Green_Lifecycle: Active; Shrouded: N; Gender: Male; Green_REACh: Passed; Voltage_V: 1.8kV; Row_Count: 1; Pitch_mm: 2.54; CT: FALSE; Cert_UL: Y
J5 = CMP-0055971-1: Connector, 100 Pos. 0.635mm, SMT; Manufacturer: Samtec; CNHeader: FALSE; Green_Lifecycle: Active; Green_REACh: Passed
J6 = CMP-0055127-1: Binding Post, RED, TH; Manufacturer: Keystone; PartNumber: 7006; CNHeader: FALSE; Green_Lifecycle: Active; Green_REACh: Passed; CompType: Connector
J7 = CMP-0055128-1: Binding Post, BLACK, TH; Manufacturer: Keystone; PartNumber: 7007; CNHeader: FALSE; Green_Lifecycle: Active; Green_REACh: Passed; CompType: Connector
R7 = CMP-0026699-1: RES, 470, 1%, 0.1 W, AEC-Q200 Grade 0, 0402; Manufacturer: Panasonic; Power_W: 100mW; TempCo: 100 ppm/C; Value_Code: 470R; U/M: EA; Value: 470; SizeX_mm: 1; SizeY_mm: 0.5; SizeZ_mm: 0.6; Value2: 0.1W; CompType: Resistor; AEC Qualified: Y; VDC_V: 50V; AEC Grade: 0; AEC Category: Q200
R8 R10 R16 R19 = CMP-0026754-1: as R20 on sheet AMPS023A_BTL1
R9 = CMP-0026754-1: RES, 10.0 k, 1%, 0.063 W, AEC-Q200 Grade 0, 0402; Manufacturer: Stackpole Electronics Inc; PartNumber: RMCF0402FT10K0; Power_W: 63mW; TempCo: 100 ppm/C; Value_Code: 10k0; U/M: EA; Value: 10.0k; EIA_Code: E96; Res_ohm: 10k; SizeX_mm: 1; SizeY_mm: 0.5; SizeZ_mm: 0.6; Value2: 0.063W; CompType: Resistor; AEC Qualified: Y; VDC_V: 50V; AEC Grade: 0; AEC Category: Q200
R11 R12 = CMP-0026729-1: RES, 2.20 k, 1%, 0.063 W, 0402; Manufacturer: Yageo America; Power_W: 63mW; TempCo: 100 ppm/C; Value_Code: 2k20; U/M: EA; Value: 2.20k; Res_ohm: 2.2k; SizeX_mm: 1; SizeY_mm: 0.5; SizeZ_mm: 0.6; Value2: 0.063W; CompType: Resistor; AEC Qualified: N; AEC Category: Q200
R13 R14 = CMP-0025874-3: RES, 0, 5%, 0.1 W, 0603; Manufacturer: Panasonic; Power_W: 100mW; TempCo: 600 ppm/C; Value_Code: 0000; U/M: EA; Value: 0; EIA_Code: E24; SizeX_mm: 1.6; SizeY_mm: 0.8; SizeZ_mm: 1; Value2: 0.1W; SizeArea_mm2: 1.28; CompType: Resistor; VDC_V: 50V; AEC Category: Q200
R15 R18 = CMP-0026738-1: RES, 49.9, 1%, 0.063 W, 0402; Manufacturer: Yageo America; Power_W: 63mW; TempCo: 100 ppm/C; Value_Code: 49R9; U/M: EA; Value: 49.9; EIA_Code: E96; SizeX_mm: 1; SizeY_mm: 0.5; SizeZ_mm: 0.6; Value2: 0.063W; CompType: Resistor; AEC Qualified: N; VDC_V: 50V; AEC Category: Q200
TP1 = CMP-0055137-1: Test Point, Miniature, Red, TH; Manufacturer: Keystone; PartNumber: 5000; CNHeader: FALSE; Green_Lifecycle: Active; Green_REACh: Passed; ContactFinish: Silver; CT: TRUE
TP2 TP3 = CMP-0055138-1: Test Point, Miniature, Black, TH; Manufacturer: Keystone; PartNumber: 5001; CNHeader: FALSE; Green_Lifecycle: Active; Green_REACh: Passed; ContactFinish: Silver; CT: TRUE
TP4-TP18 = CMP-0055140-1: Test Point, Miniature, Orange, TH; Manufacturer: Keystone; PartNumber: 5003; CNHeader: FALSE; Green_Lifecycle: Active; Green_REACh: Passed; ContactFinish: Silver; CT: TRUE
U3 = CMP-0005242-2: EEPROM, 512KBIT, 400KHZ, 8TSSOP; Manufacturer: Microchip; SizeAreaWB_mm2: 42; SizeZ_mm: 1.2; SizeX_mm: 6.4; SizeY_mm: 3; SizeArea_mm2: 19.2
U4 U5 = CMP-0051026-1: Single 2-Line to 1-Line Data Selector/Multiplexer, DCU0008A, LARGE T&R; Generic Part Number: SN74LVC2G157; Manufacturer: Texas Instruments; Voltage(Nom)(V): 1.8,2.5,3.3,5; Logic: True; tpd @ Nom Voltage(Max)(ns): 14,8,6,4; Bits(#): 2; Schmitt Trigger: No; VCC(Min)(V): 1.65; F @ Nom Voltage(Max)(Mhz): 150; Output Drive (IOL/IOH)(Max)(mA): 32/-32; VCC(Max)(V): 5.5; Technology Family: LVC; Sub-Family: Decoder/Encoder/Multiplexer; Input Type: CMOS/TTL; ICC @ Nom Voltage(Max)(mA): 0.01; Rating: Catalog; Output Type: CMOS

## Sheet AMPS023A_EVM_Hardware.SchDoc: Hardware
size Letter; Date: Not shown in title block; ApprovedBy: Not shown in title block; CheckedBy: Not shown in title block; Author: Not shown in title block; CompanyName: Not shown in title block; DrawnBy: LDN; Engineer: Not shown in title block; Organization: Not shown in title block; Address1: Not shown in title block; Address2: Not shown in title block; Address3: Not shown in title block; Address4: Not shown in title block; DocumentNumber: 4; Revision: Use project parameter SCH_Rev; SheetNumber: 4; SheetTotal: 4; PageSetup: Record=PageOptions¦CenterHorizontal=True¦CenterVertical=True¦PrintScale=1.00¦XCorrection=1.00¦YCorrection=1.00¦PrintKind=0¦BorderSize=5000000¦LeftOffset=0¦BottomOffset=0¦Orientation=2¦PaperLength=1000¦PaperWidth=1000¦Scale=100¦PaperSource=15¦PrintQuality=600¦MediaType=1¦DitherType=10¦PaperKind=Letter¦PrintScaleMode=1
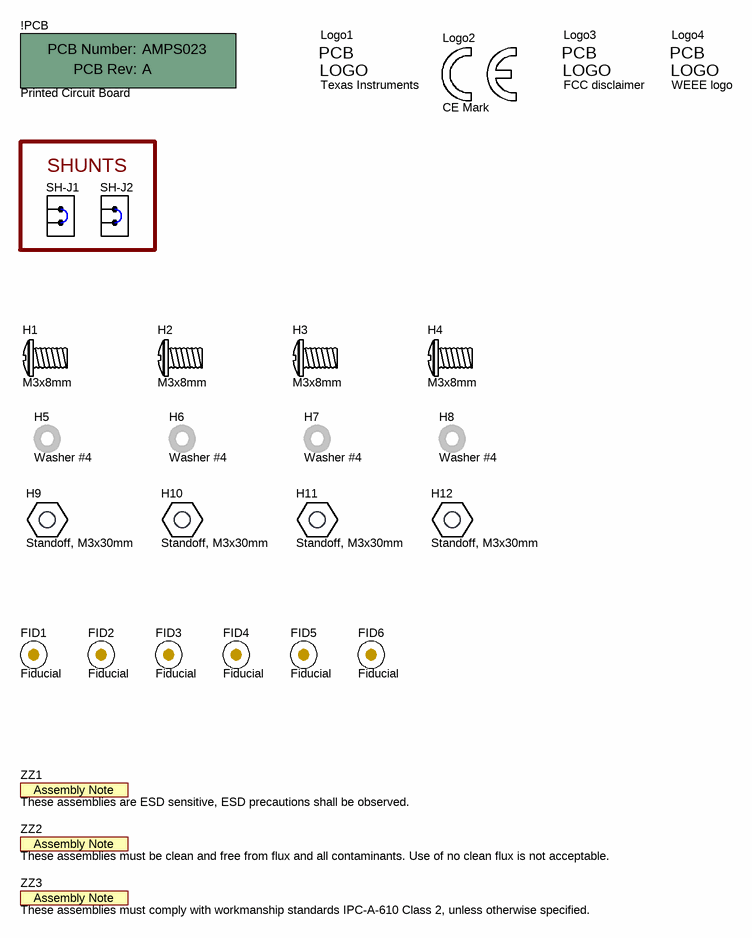
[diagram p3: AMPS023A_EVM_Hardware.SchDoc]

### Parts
!PCB  Printed Circuit Board  (mechanical)
FID1  CompType: Fiducial  [Fiducial6.4-20]  (hidden comment: DNP)
FID2  CompType: Fiducial  [Fiducial6.4-20]  (hidden comment: DNP)
FID3  CompType: Fiducial  [Fiducial6.4-20]  (hidden comment: DNP)
FID4  CompType: Fiducial  [Fiducial6.4-20]  (hidden comment: DNP)
FID5  CompType: Fiducial  [Fiducial6.4-20]  (hidden comment: DNP)
FID6  CompType: Fiducial  [Fiducial6.4-20]  (hidden comment: DNP)
H1  M3x8mm  [APM_RM3X8MM 2701]  (mechanical)
H2  M3x8mm  [APM_RM3X8MM 2701]  (mechanical)
H3  M3x8mm  [APM_RM3X8MM 2701]  (mechanical)
H4  M3x8mm  [APM_RM3X8MM 2701]  (mechanical)
H5  Washer #4  (mechanical)
H6  Washer #4  (mechanical)
H7  Washer #4  (mechanical)
H8  Washer #4  (mechanical)
H9  Standoff, M3x30mm  [Harwin_R30-1003002]
H10  Standoff, M3x30mm  [Harwin_R30-1003002]
H11  Standoff, M3x30mm  [Harwin_R30-1003002]
H12  Standoff, M3x30mm  [Harwin_R30-1003002]
Logo1  Texas Instruments  [TI_Stacked_Overlay_Small]  (no BOM)
Logo2  CE Mark  [CE_Mark_5mm]  (no BOM)
Logo3  FCC disclaimer  [FCC_disclaimer_stacked]  (no BOM)
Logo4  WEEE logo  [WEEE_Minimum]  (no BOM)
SH-J1  SNT-100-BK-G  [SNT-100-BK-G]  (value not drawn)
SH-J2  SNT-100-BK-G  [SNT-100-BK-G]  (value not drawn)
ZZ1  These assemblies are ESD sensitive, ESD precautions shall be observed.  [AssemblyNote]  (no BOM)
ZZ2  These assemblies must be clean and free from flux and all contaminants. Use of no clean flux is not acceptable.  [AssemblyNote]  (no BOM)
ZZ3  These assemblies must comply with workmanship standards IPC-A-610 Class 2, unless otherwise specified.  [AssemblyNote]  (no BOM)

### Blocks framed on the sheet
SHUNTS: SH-J1 SH-J2

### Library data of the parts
!PCB = CMP-0003618-2: PartNumber: AMPS023; Manufacturer: Any
FID1-FID6 = CMP-0077181-1: Fiducial mark.  There is nothing to buy or mount.
H1-H4 = CMP-0003717-1: MACHINE SCREW PAN PHILLIPS M3; Manufacturer: APM HEXSEAL; Key: RM3X8MM 2701; CompType: Standoff
H5-H8 = CMP-0003675-1: Washer, Flat, #4 Nylon; Manufacturer: Keystone; Key: 3200
H9-H12 = CMP-0003674-1: Standoff, HexBrass M3, 30 mm; Manufacturer: Harwin; Key: R30-1003002; CompType: Spacer
Logo1 = CMP-0074838-1: Texas Instrument Corporate Signature; Library Reference: Logo; SymbolCreator: a0412235; Lib Reference: TI_Logo
Logo2 = CMP-0074844-1: SymbolCreator: a0412235
Logo3 = CMP-0074847-1: FCC_disclaimer; Library Reference: Logo
Logo4 = CMP-0074769-1
SH-J1 SH-J2 = CMP-0003623-1: Shunt, 100mil, Gold plated, Black; Alternate PartNumber: 969102-0000-DA; Manufacturer: Samtec; Alternate Manufacturer: 3M; Value: 1x2
ZZ1 = CMP-0077236-1
ZZ2 = CMP-0077237-1
ZZ3 = CMP-0077238-1

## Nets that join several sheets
DVDD1: AMPS023A_BTL1 (8 pins), AMPS023A_PPCMB-IO (J2.2)
DVDD2: AMPS023A_BTL2 (8 pins), AMPS023A_PPCMB-IO (J3.2)
GND: AMPS023A_BTL1 (23 pins), AMPS023A_BTL2 (25 pins), AMPS023A_PPCMB-IO (42 pins)
PVDD1: AMPS023A_BTL1 (10 pins), AMPS023A_PPCMB-IO (J10.1)
PVDD2: AMPS023A_BTL2 (12 pins), AMPS023A_PPCMB-IO (J1.1)
~{FAULT1}: AMPS023A_BTL1 (R20.1 U1.9), AMPS023A_PPCMB-IO (J5.22 TP4.1)
~{FAULT2}: AMPS023A_BTL2 (R3.1 U2.9), AMPS023A_PPCMB-IO (J5.24 TP5.1)
~{MUTE1}: AMPS023A_BTL1 (R21.1 U1.10), AMPS023A_PPCMB-IO (J5.78 TP14.1 U4.2 U5.1)
~{MUTE2}: AMPS023A_BTL2 (R4.1 U2.10), AMPS023A_PPCMB-IO (J5.98 TP15.1 U5.2)
~{PDN1}: AMPS023A_BTL1 (R23.1 U1.17), AMPS023A_PPCMB-IO (J5.90 TP18.1)
~{PDN2}: AMPS023A_BTL2 (R6.1 U2.17), AMPS023A_PPCMB-IO (J5.86 TP17.1)
~{WARN1}: AMPS023A_BTL1 (R22.1 U1.11), AMPS023A_PPCMB-IO (J5.34 TP8.1)
~{WARN2}: AMPS023A_BTL2 (R5.1 U2.11), AMPS023A_PPCMB-IO (J5.28 TP9.1)
LRCLK: AMPS023A_BTL1 (U1.12), AMPS023A_BTL2 (U2.12), AMPS023A_PPCMB-IO (J5.47 TP11.1)
SCL: AMPS023A_BTL1 (U1.16), AMPS023A_BTL2 (U2.16), AMPS023A_PPCMB-IO (R11.1 R13.1 TP6.1)
SCLK: AMPS023A_BTL1 (U1.13), AMPS023A_BTL2 (U2.13), AMPS023A_PPCMB-IO (J5.45 TP12.1)
SDA: AMPS023A_BTL1 (U1.15), AMPS023A_BTL2 (U2.15), AMPS023A_PPCMB-IO (R12.1 R14.1 TP7.1)
SDIN1: AMPS023A_BTL1 (U1.14), AMPS023A_PPCMB-IO (J5.49 TP10.1 U4.1)
SDIN2: AMPS023A_BTL2 (U2.14), AMPS023A_PPCMB-IO (R18.2 TP16.1)

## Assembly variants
001: not fitted FID1 FID2 FID3 FID4 FID5 FID6 R9 R17 R24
